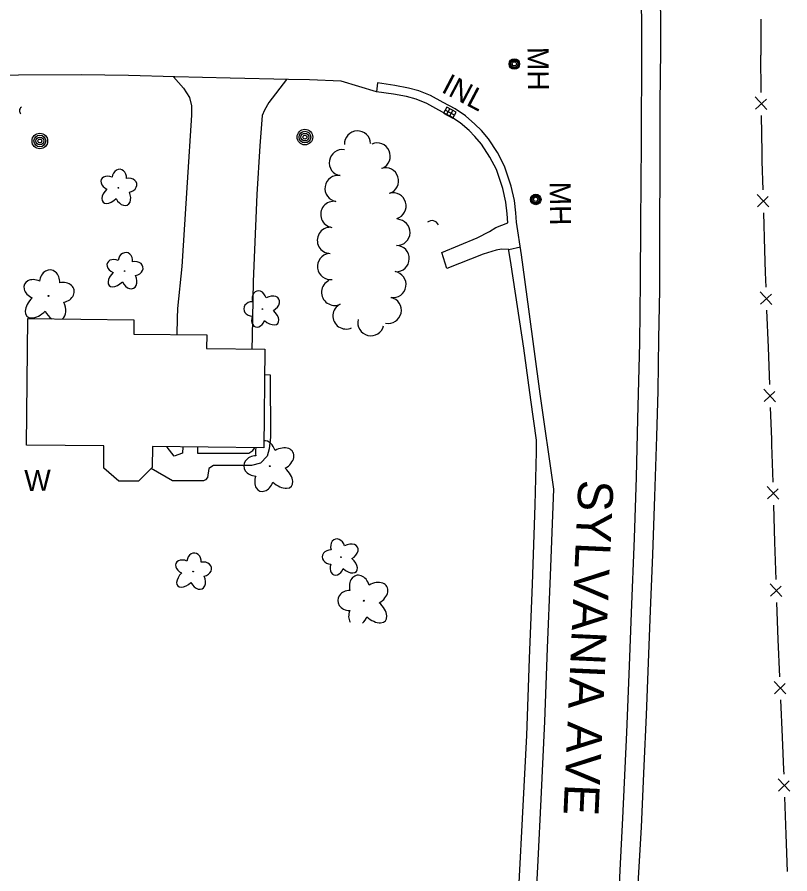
# Model space of a CAD drawing. Extents: x 588843 to 2552415, y 180129 to 269402.
# Drawn here: x 593686.1 to 593906.8, y 188744.2 to 188988.9 of the extents above; entities that cross this region are included whole.
import ezdxf

# ---------------------------------------------------------------- set-up
doc = ezdxf.new("R2010")
doc.units = 0
for name, color, linetype in [('Default', 7, 'Continuous'), ('E_BLD', 7, 'Continuous'), ('E_DRN', 7, 'Continuous'), ('E_DRN_Text', 7, 'Continuous'), ('E_DWY', 7, 'Continuous'), ('E_FEN_P', 7, 'Continuous'), ('E_LAND_TreeLine_P', 7, 'Continuous'), ('E_LAND_Vegetation', 7, 'Continuous'), ('E_MISCPROP', 7, 'Continuous'), ('E_PATH_Sidewalk', 7, 'Continuous'), ('E_RDWY', 7, 'Continuous'), ('E_RDWY_C_and_G', 7, 'Continuous'), ('E_RDWY_Gravel', 7, 'Continuous'), ('E_RDWY_Text', 7, 'Continuous'), ('E_UTL_MH', 7, 'Continuous'), ('E_UTL_MH_Text', 7, 'Continuous'), ('E_WAL_Text', 7, 'Continuous')]:
    doc.layers.add(name, color=color, linetype=linetype)

# ---------------------------------------------------------------- blocks, each defined once
blk = doc.blocks.new('MHO')
at = {"layer": 'Default'}
for centre, radius in [((0.08, -0.12), 3), ((0.08, -0.12), 2.43), ((0.07, -0.15), 1.94), ((0.02, -0.16), 1.21)]:
    blk.add_circle(centre, radius, dxfattribs=at)
blk = doc.blocks.new('MHT')
at = {"layer": 'E_UTL_MH_Text'}
blk.add_text('MH', height=12, dxfattribs=at).set_placement((-9.81, -6))
blk = doc.blocks.new('INLO')
at = {"layer": 'E_DRN'}
for p, q in [((2, -4), (2, 0)), ((4, -4), (4, 0)), ((6, -2), (0, -2))]:
    blk.add_line(p, q, dxfattribs=at)
blk.add_lwpolyline([(0, -4), (6, -4), (6, 0), (0, 0), (0, -4)], close=True, dxfattribs=at)
blk = doc.blocks.new('INLT_35')
at = {"layer": 'E_DRN_Text'}
blk.add_text('INL', height=12, dxfattribs=at).set_placement((-11.03, -6))
blk = doc.blocks.new('CULV2')
at = {"layer": 'E_DRN'}
blk.add_arc((19.7, 14.8), 24.6, 216.8699, 323.1301, dxfattribs=at)
blk = doc.blocks.new('POLE')
at = {"layer": 'Default'}
for radius in [4.46, 3.35, 2.23, 1.12]:
    blk.add_circle((0, 0), radius, dxfattribs=at)
blk = doc.blocks.new('W_29')
at = {"layer": 'E_WAL_Text'}
blk.add_text('W', height=12, dxfattribs=at).set_placement((-4.46, -6))
blk = doc.blocks.new('DTRE')
at = {"layer": 'Default'}
blk.add_circle((-0.18, 0), 0.183, dxfattribs=at)
for centre, major_axis, ratio in [((-1.87, 5.32), (1.36, -4.98), 0.782863), ((4.06, 2.74), (-5.27, -2.93), 0.691916), ((-5.87, 0.15), (4.93, -0.12), 0.832022), ((-2.49, -5.24), (1.8, 4.86), 0.716896), ((3.54, -3.71), (-5.01, 4.58), 0.560249)]:
    blk.add_ellipse(centre, major_axis=major_axis, ratio=ratio, start_param=1.570796, end_param=4.712389, dxfattribs=at)
blk = doc.blocks.new('U311')
at = {"layer": 'E_LAND_Vegetation'}
blk.add_circle((-0.09, 0.01), 0.128, dxfattribs=at)
for centre, major_axis, ratio, start_param, end_param in [((-1.31, 3.72), (0.99, -3.48), 0.782863, 1.570796, 2.959084), ((-1.31, 3.72), (0.99, -3.48), 0.782863, 4.039203, 4.712389), ((2.86, 1.95), (-3.67, -2.09), 0.691916, 1.570796, 4.712389), ((-4.07, 0.07), (3.45, -0.05), 0.832022, 1.570796, 4.712389), ((2.54, -2.56), (-3.54, 3.17), 0.560249, 1.570796, 4.712389), ((-1.67, -3.68), (1.23, 3.41), 0.716896, 1.570796, 4.712389)]:
    blk.add_ellipse(centre, major_axis=major_axis, ratio=ratio, start_param=start_param, end_param=end_param, dxfattribs=at)
blk = doc.blocks.new('U312')
at = {"layer": 'E_LAND_Vegetation'}
blk.add_circle((0.01, 0.09), 0.128, dxfattribs=at)
for centre, major_axis, ratio, start_param, end_param in [((0.36, 4.06), (-0.3, -3.44), 0.832022, 1.570796, 4.712389), ((-3.55, 1.93), (3.32, -1.47), 0.716896, 1.570796, 4.712389), ((3.8, 1.04), (-3.54, -0.74), 0.782863, 1.570796, 4.712389), ((-2.74, -2.35), (3.42, 3.31), 0.560249, 1.570796, 4.712389), ((1.74, -2.99), (-1.82, 3.81), 0.691916, 3.327153, 4.712389), ((1.74, -2.99), (-1.82, 3.81), 0.691916, 1.570796, 2.30084)]:
    blk.add_ellipse(centre, major_axis=major_axis, ratio=ratio, start_param=start_param, end_param=end_param, dxfattribs=at)

msp = doc.modelspace()

# ---------------------------------------------------------------- linework, layer by layer
at = {"layer": 'E_BLD'}
msp.add_lwpolyline([(593756.56, 188865.9), (593724.76, 188866.25), (593724.69, 188860.27), (593720.75, 188856.33), (593715.15, 188856.39), (593710.86, 188860.07), (593710.93, 188866.43), (593688.77, 188866.67), (593689.16, 188902.8), (593719.49, 188902.47), (593719.45, 188898.36), (593740.27, 188898.13), (593740.23, 188894.26), (593756.87, 188894.08), (593756.56, 188865.9)], close=True, dxfattribs=at)
at = {"layer": 'E_DWY'}
for points in [[(593730.83, 188971.82), (593733.6, 188968.62), (593735.35, 188965.98), (593735.93, 188963.52), (593735.93, 188960.88), (593734.68, 188941.67), (593733.18, 188917.72), (593731.95, 188905.69), (593731.82, 188902.91), (593731.73, 188898.22)], [(593763.1, 188971.11), (593757.99, 188964.5), (593756.75, 188962.37), (593756.07, 188960.82), (593755.44, 188952.18), (593754.58, 188938.21), (593753.52, 188913.35), (593753.22, 188897.68), (593753.15, 188894.12)]]:
    msp.add_lwpolyline(points, dxfattribs=at)
at = {"layer": 'E_FEN_P'}
for p, q in [((593900.18, 188962.48), (593896.91, 188966.14)), ((593896.95, 188962.61), (593900.08, 188965.43)), ((593900.77, 188934.68), (593897.43, 188938.28)), ((593897.54, 188934.75), (593900.61, 188937.63)), ((593901.68, 188906.87), (593898.32, 188910.45)), ((593898.45, 188906.92), (593901.5, 188909.82)), ((593902.72, 188879.06), (593899.36, 188882.64)), ((593899.49, 188879.11), (593902.54, 188882.01)), ((593903.63, 188851.23), (593900.3, 188854.83)), ((593900.41, 188851.3), (593903.48, 188854.18)), ((593904.47, 188823.41), (593901.14, 188827.01)), ((593901.25, 188823.48), (593904.32, 188826.36)), ((593905.65, 188795.62), (593902.27, 188799.18)), ((593902.42, 188795.65), (593905.46, 188798.57)), ((593906.79, 188767.8), (593903.44, 188771.39)), ((593903.56, 188767.86), (593906.62, 188770.75))]:
    msp.add_line(p, q, dxfattribs=at)
for points in [[(593898.5, 188988.29), (593898.49, 188978.03)], [(593898.63, 188967.4), (593898.49, 188978.03)], [(593898.85, 188950.2), (593898.71, 188960.83)], [(593899.13, 188939.58), (593898.88, 188947.79), (593898.85, 188950.2)], [(593899.65, 188922.38), (593899.33, 188933)], [(593900, 188911.76), (593899.85, 188916), (593899.65, 188922.38)], [(593900.65, 188894.56), (593900.25, 188905.18)], [(593901.04, 188883.94), (593900.65, 188894.56)], [(593901.68, 188866.75), (593901.63, 188868.4), (593901.29, 188877.37)], [(593902, 188856.13), (593901.68, 188866.75)], [(593902.51, 188838.93), (593902.19, 188849.55)], [(593902.84, 188828.3), (593902.51, 188838.93)], [(593903.49, 188811.11), (593903.04, 188821.73)], [(593903.95, 188800.49), (593903.49, 188811.11)], [(593904.69, 188783.3), (593904.23, 188793.92)], [(593905.14, 188772.69), (593905.09, 188773.95), (593904.69, 188783.3)], [(593905.72, 188755.49), (593905.36, 188766.11)], [(593906.07, 188744.87), (593905.72, 188755.49)]]:
    msp.add_lwpolyline(points, dxfattribs=at)
at = {"layer": 'E_LAND_TreeLine_P'}
for centre, start, end in [((593783.34, 188952.67), 2.3199, 182.3199), ((593788.94, 188949.22), 293.9091, 113.9091), ((593778.98, 188947.32), 80.6453, 260.6453), ((593791.34, 188942.14), 288.139, 108.139), ((593777.77, 188939.94), 80.6453, 260.6453), ((593793.5, 188934.97), 286.6558, 106.6558), ((593776.56, 188932.55), 80.7216, 260.7216), ((593794.61, 188927.41), 268.341, 88.341), ((593775.58, 188925.14), 88.7789, 268.7789), ((593794.39, 188919.93), 268.341, 88.341), ((593775.62, 188917.67), 97.8375, 277.8375), ((593793.47, 188912.52), 260.8241, 80.8241), ((593776.8, 188910.31), 115.6961, 295.6961), ((593792.11, 188905.16), 257.8295, 77.8295), ((593780.04, 188903.56), 115.6961, 295.6961), ((593787.16, 188901.63), 166.6481, 346.6481)]:
    msp.add_arc(centre, 3.74, start, end, dxfattribs=at)
at = {"layer": 'E_LAND_Vegetation'}
msp.add_circle((593785.12, 188822.22), 0.128, dxfattribs=at)
for centre, major_axis, ratio, start_param, end_param in [((593783.9, 188825.93), (0.99, -3.48), 0.782863, 1.570796, 4.712389), ((593788.07, 188824.16), (-3.67, -2.09), 0.691916, 1.570796, 4.712389), ((593781.14, 188822.28), (3.45, -0.05), 0.832022, 1.570796, 4.712389), ((593787.75, 188819.65), (-3.54, 3.17), 0.560249, 1.570796, 4.712389), ((593783.54, 188818.53), (1.23, 3.41), 0.716896, 1.570796, 2.581423), ((593783.54, 188818.53), (1.23, 3.41), 0.716896, 4.079468, 4.712389)]:
    msp.add_ellipse(centre, major_axis=major_axis, ratio=ratio, start_param=start_param, end_param=end_param, dxfattribs=at)
at = {"layer": 'E_PATH_Sidewalk'}
for points in [[(593756.79, 188886.8), (593758.43, 188886.72), (593758.53, 188868.94), (593758.11, 188865.6), (593757.55, 188863.53), (593755.67, 188861.54), (593753.06, 188860.81), (593742.2, 188860.84), (593740.85, 188860.03), (593740.46, 188857.42), (593739.96, 188856.75), (593739.35, 188856.43), (593730.5, 188856.48), (593724.37, 188859.95)], [(593733.41, 188866.15), (593733.36, 188864.35), (593730.99, 188863.48), (593728.95, 188866.09), (593728.9, 188866.2)], [(593737.62, 188866.11), (593737.64, 188864.4), (593749.59, 188864.4), (593752.31, 188864.36), (593753.45, 188865.09), (593753.92, 188865.76), (593753.93, 188865.93)]]:
    msp.add_lwpolyline(points, dxfattribs=at)
at = {"layer": 'E_RDWY'}
msp.add_line((593826.51, 188922.49), (593829.83, 188923.34), dxfattribs=at)
for points in [[(593864.52, 188979.52), (593864.42, 189000.3), (593864.35, 189018.08), (593864.32, 189037.07), (593864.27, 189057.45), (593864.2, 189081.63), (593864.08, 189098.52), (593863.93, 189123.43), (593863.83, 189149.07), (593863.74, 189180.82), (593863.69, 189201.96), (593863.58, 189227)], [(593857.66, 188729.92), (593858.35, 188745.25), (593859.12, 188760.11), (593860.25, 188784.61), (593860.97, 188803.63), (593861.61, 188818.78), (593862.39, 188840.07), (593863.01, 188857.49), (593863.39, 188874.12), (593863.94, 188895.91), (593864.15, 188913.43), (593864.24, 188930.09), (593864.38, 188952.86), (593864.52, 188979.52)], [(593788.77, 188967.53), (593778.7, 188970.59), (593769.59, 188970.95), (593763.58, 188971.09), (593746.97, 188971.45), (593731.2, 188971.8), (593717.95, 188972.25), (593704.44, 188972.42), (593686.53, 188972.34), (593680.81, 188972.17)], [(593826.51, 188922.49), (593824.47, 188922.59), (593822.97, 188922.35), (593819.25, 188921.22), (593808.81, 188917.09), (593807.45, 188921.63), (593817.53, 188925.82), (593821.02, 188927.69), (593822.81, 188928.8), (593826.27, 188930.13)], [(593833.97, 188729.84), (593834.9, 188748.08), (593835.73, 188765.52), (593836.78, 188787.75), (593837.61, 188808.65), (593838.47, 188829.45), (593839.37, 188854.04), (593835.51, 188881.28), (593832.24, 188905.45), (593830.2, 188920.99), (593828.76, 188930.3)]]:
    msp.add_lwpolyline(points, dxfattribs=at)
at = {"layer": 'E_RDWY_C_and_G'}
msp.add_line((593789.07, 188970.12), (593788.77, 188967.53), dxfattribs=at)
for points in [[(593828.76, 188930.3), (593828.58, 188932.96), (593828.18, 188936.52), (593827.22, 188940.65), (593825.31, 188946.37), (593823.29, 188950.21), (593820.71, 188954.11), (593818.71, 188956.51), (593816.88, 188958.35), (593814.16, 188960.74), (593811.18, 188962.67), (593807.76, 188964.55), (593804.18, 188966.47), (593800.87, 188967.84), (593797.85, 188968.65), (593793.98, 188969.33), (593789.07, 188970.12)], [(593826.27, 188930.13), (593826.09, 188932.73), (593825.71, 188936.09), (593824.81, 188939.97), (593823, 188945.39), (593821.13, 188948.94), (593818.7, 188952.61), (593816.85, 188954.83), (593815.17, 188956.53), (593812.65, 188958.75), (593809.89, 188960.52), (593806.57, 188962.35), (593803.11, 188964.21), (593800.07, 188965.47), (593797.31, 188966.2), (593793.59, 188966.86), (593788.77, 188967.53)]]:
    msp.add_lwpolyline(points, dxfattribs=at)
at = {"layer": 'E_RDWY_Gravel'}
for points in [[(593869.9, 188979.4), (593869.86, 189002.24), (593869.59, 189026.59), (593869.55, 189048.3), (593869.4, 189066.64), (593869.16, 189089.81), (593869.13, 189113.91), (593868.92, 189147.41), (593868.87, 189167.95), (593868.78, 189189.66), (593868.72, 189215.05)], [(593856.86, 188620.02), (593857.9, 188638), (593859.01, 188656.64), (593860.02, 188671.39), (593860.94, 188687.22), (593861.83, 188707.08), (593862.62, 188724), (593863.48, 188741.36), (593864.4, 188757.55), (593865.2, 188775.04), (593865.81, 188789.54), (593866.45, 188804.55), (593867.01, 188819.34), (593867.62, 188835.4), (593868.27, 188852.03), (593868.81, 188869.08), (593869.15, 188882.17), (593869.42, 188897.04), (593869.64, 188911.04), (593869.64, 188928.9), (593869.76, 188945.61), (593869.78, 188964.35), (593869.9, 188979.4)], [(593829.43, 188739.84), (593830.63, 188763.61), (593831.65, 188783.77), (593832.45, 188805.77), (593833.27, 188826.95), (593834.07, 188849.47), (593834.42, 188864.73), (593834.43, 188868.06), (593832.87, 188879.57), (593830.8, 188894.35), (593827.21, 188918.14), (593826.54, 188922.29), (593826.51, 188922.49)]]:
    msp.add_lwpolyline(points, dxfattribs=at)

# ---------------------------------------------------------------- block references
at = {"layer": 'E_DRN'}
for name, p, xscale, yscale, rotation in [('CULV2', (593687.34, 188963.15), 0.04770858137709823, 0.047708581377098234, -93.72458973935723), ('INLO', (593808.84, 188963.21), 0.4999999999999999, 0.5000000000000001, -28.61341743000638), ('CULV2', (593806.45, 188929.59), 0.08085961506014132, 0.08085961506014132, 167.0942125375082)]:
    msp.add_blockref(name, p, dxfattribs=dict(at, xscale=xscale, yscale=yscale, rotation=rotation))
at = {"layer": 'E_DRN_Text', "xscale": 0.4999999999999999, "yscale": 0.4999999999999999, "rotation": -27.779860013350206}
msp.add_blockref('INLT_35', (593813.27, 188967.73), dxfattribs=at)
at = {"layer": 'E_LAND_Vegetation'}
for p, xscale, yscale, rotation in [((593715.06, 188940.07), 0.4999999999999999, 0.5, -93.51471597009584), ((593716.82, 188916.28), 0.4999999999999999, 0.5, -93.51471597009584), ((593756.26, 188905.51), 0.4999999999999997, 0.4999999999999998, 0.577990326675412), ((593778.68, 188834.67), 0.4999999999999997, 0.4999999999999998, 0.577990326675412), ((593736.41, 188830.45), 0.4999999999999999, 0.5, -93.51471597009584)]:
    msp.add_blockref('DTRE', p, dxfattribs=dict(at, xscale=xscale, yscale=yscale, rotation=rotation))
for name, p in [('U312', (593695.07, 188909.19)), ('U311', (593758.37, 188860.64))]:
    msp.add_blockref(name, p, dxfattribs=at)
at = {"layer": 'E_MISCPROP', "xscale": 0.4999999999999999, "yscale": 0.4999999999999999, "rotation": -27.779860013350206}
for p in [(593692.62, 188953.52), (593768.3, 188954.64)]:
    msp.add_blockref('POLE', p, dxfattribs=at)
at = {"layer": 'E_UTL_MH', "xscale": 0.5, "yscale": 0.5, "rotation": -89.32254181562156}
for p in [(593828.18, 188975.56), (593834.29, 188936.86)]:
    msp.add_blockref('MHO', p, dxfattribs=at)
at = {"layer": 'E_UTL_MH_Text', "xscale": 0.5, "yscale": 0.5, "rotation": -89.32254181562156}
for p in [(593834.92, 188975.48), (593841.26, 188936.98)]:
    msp.add_blockref('MHT', p, dxfattribs=at)
at = {"layer": 'E_WAL_Text', "xscale": 0.4999999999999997, "yscale": 0.4999999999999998, "rotation": 0.577990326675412}
msp.add_blockref('W_29', (593690.42, 188856.58), dxfattribs=at)

# ---------------------------------------------------------------- texts
at = {"layer": 'E_RDWY_Text'}
msp.add_text('SYLVANIA AVE', height=10, rotation=267.4132, dxfattribs=at).set_placement((593846.46, 188856.89))

doc.saveas('drawing.dxf')
